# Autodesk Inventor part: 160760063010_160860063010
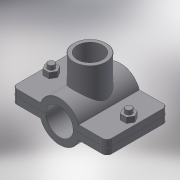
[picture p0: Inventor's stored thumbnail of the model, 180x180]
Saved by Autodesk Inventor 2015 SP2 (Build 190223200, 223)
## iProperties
Created: 2017-05
Part Number: 160760063010_160860063010
Material: Generic
Description: PLASSON SADDLE 63-1"
Document SubType Name: Modeling
Designer: KIM
Density: 1 g/cm^3
Appearance: Default
Author: KIM
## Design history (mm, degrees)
derived "16076.ipt"
feature "Solid1::16076.ipt"
feature "Solid2::16076.ipt"
tag "TaggingFeature1"
body "Solid1"
other parameters: "d0" = 78.75, "d1" = 116, "d2" = 31.5, "d3" = 63, "d4" = 84, "d5" = 0, "d6" = 5.8, "d7" = 116, "d8" = 0.1, "d10" = 0, "d11" = 0.63, "d14" = 39.3783, "d20" = 0.63, "d23" = 0.63, "d37" = 8, "d38" = 39.5, "d39" = 0, "d40" = 3, "d41" = 5, "d42" = 0, "d43" = 6, "d44" = 3, "d45" = 0, "d46" = 0.63, "d51" = 61, "d52" = 30.291, "d53" = 21, "d54" = 0, "d55" = 25, "d57" = 0, "d58" = 68.04, "d60" = 0, "d63" = 8, "d66" = 68, "d_" = 63, "B_" = 25, "G_" = 30.291, "A_" = 61, "L_" = 116, "L_1" = 84, "l_2" = 21
